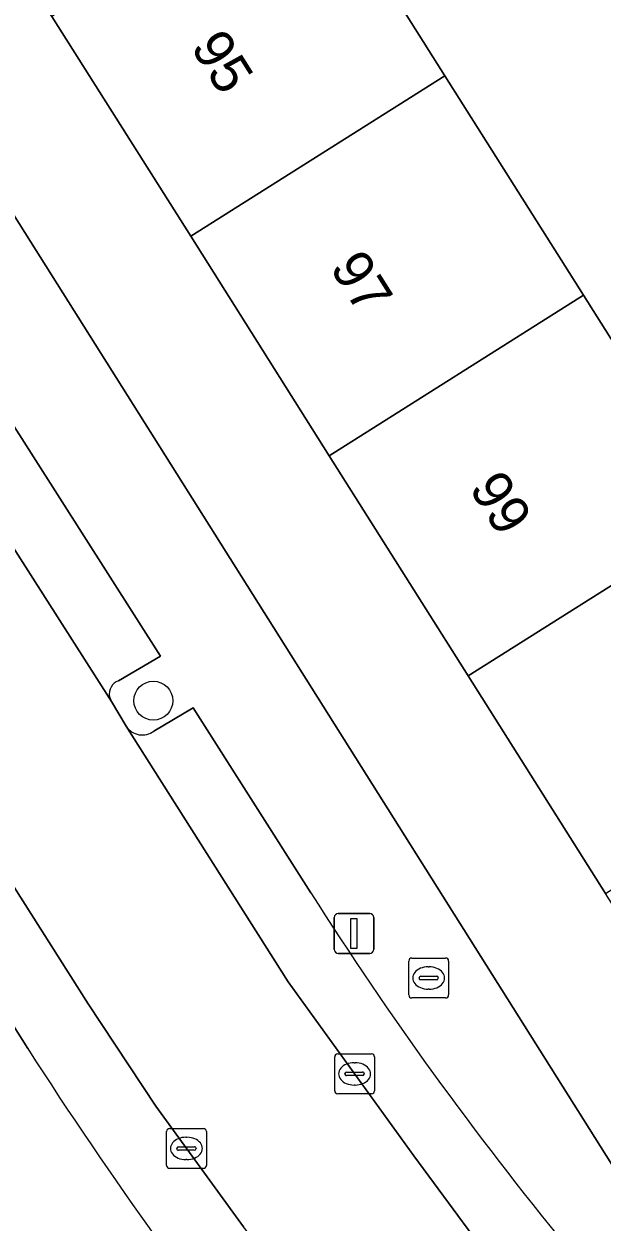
# Model space of a CAD drawing. Extents: x 162344 to 162869, y 381217 to 381818.
# Drawn here: x 162612.92 to 162627.44, y 381421.83 to 381451.9 of the extents above; entities that cross this region are included whole.
import ezdxf

# ---------------------------------------------------------------- set-up
doc = ezdxf.new("R2010")
doc.units = 0
for name, color, linetype in [('IMGEO_Boom', 7, 'Continuous'), ('IMGEO_Brandkraan', 7, 'Continuous'), ('IMGEO_Erf', 7, 'Continuous'), ('IMGEO_Kolk', 7, 'Continuous'), ('IMGEO_Lichtmast', 7, 'Continuous'), ('IMGEO_Pand', 7, 'Continuous'), ('IMGEO_Pand_nummerreeks', 7, 'Continuous'), ('IMGEO_Parkeervlak_open', 7, 'Continuous'), ('IMGEO_Rijbaan_lokaal_gesloten', 7, 'Continuous'), ('IMGEO_Voetpad_open', 7, 'Continuous')]:
    doc.layers.add(name, color=color, linetype=linetype)

msp = doc.modelspace()

# ---------------------------------------------------------------- linework, layer by layer
at = {"layer": 'IMGEO_Boom'}
msp.add_circle((162616.169, 381434.913), 0.489, dxfattribs=at)
at = {"layer": 'IMGEO_Brandkraan'}
for p, q in [((162622.582, 381427.527), (162622.582, 381428.379)), ((162622.657, 381428.453), (162623.509, 381428.453)), ((162623.583, 381428.379), (162623.583, 381427.527)), ((162622.884, 381427.996), (162623.282, 381427.996)), ((162623.07, 381428.233), (162623.095, 381428.233)), ((162622.841, 381427.947), (162622.841, 381427.959)), ((162623.279, 381427.91), (162622.881, 381427.91)), ((162623.093, 381427.673), (162623.068, 381427.673)), ((162623.325, 381427.959), (162623.325, 381427.947)), ((162623.509, 381427.453), (162622.657, 381427.453))]:
    msp.add_line(p, q, dxfattribs=at)
for points in [[(162622.582, 381427.527), (162622.582, 381428.379)], [(162622.657, 381428.453), (162623.509, 381428.453)], [(162623.583, 381428.379), (162623.583, 381427.527)], [(162623.509, 381427.453), (162622.657, 381427.453)]]:
    msp.add_lwpolyline(points, dxfattribs=at)
for centre, radius, start, end in [((162622.659, 381428.377), 0.0765, 91.552, 178.448), ((162622.659, 381428.377), 0.0765, 91.552, 178.448), ((162623.507, 381428.377), 0.0765, 1.552, 88.448), ((162623.507, 381428.377), 0.0765, 1.552, 88.448), ((162622.881, 381427.956), 0.0403, 85.8775, 175.7526), ((162623.286, 381427.958), 0.0386, 1.7309, 96.639), ((162622.878, 381427.946), 0.0366, 178.938, 274.7102), ((162623.282, 381427.953), 0.043, 264.8664, 352.4533), ((162622.659, 381427.529), 0.0765, 181.552, 268.448), ((162622.659, 381427.529), 0.0765, 181.552, 268.448), ((162623.507, 381427.529), 0.0765, 271.552, 358.448), ((162623.507, 381427.529), 0.0765, 271.552, 358.448)]:
    msp.add_arc(centre, radius, start, end, dxfattribs=at)
for centre, major_axis, ratio, start_param, end_param in [((162623.069, 381427.953), (-0.387, 0.002), 0.722429, 4.712389, 7.853982), ((162623.094, 381427.953), (-0.39, 0.002), 0.717154, 1.570796, 4.712389)]:
    msp.add_ellipse(centre, major_axis=major_axis, ratio=ratio, start_param=start_param, end_param=end_param, dxfattribs=at)
at = {"layer": 'IMGEO_Erf'}
msp.add_lwpolyline([(162613.96, 381479.407), (162607.642, 381473.555), (162608.933, 381472.289), (162609.55, 381472.679), (162613.084, 381467.082), (162616.593, 381461.525), (162620.009, 381456.115), (162623.492, 381450.599), (162626.971, 381445.09), (162630.46, 381439.564)], dxfattribs=at)
msp.add_lwpolyline([(162600.252, 381466.808), (162628.211, 381422.438), (162631.131, 381424.361), (162627.522, 381430.077), (162624.077, 381435.533), (162620.587, 381441.059), (162617.109, 381446.568), (162613.625, 381452.085), (162610.21, 381457.494), (162606.701, 381463.05), (162603.166, 381468.649)], close=True, dxfattribs=at)
at = {"layer": 'IMGEO_Kolk'}
for p, q in [((162620.723, 381425.121), (162620.723, 381425.973)), ((162620.798, 381426.047), (162621.65, 381426.047)), ((162621.724, 381425.973), (162621.724, 381425.121)), ((162621.025, 381425.59), (162621.423, 381425.59)), ((162621.211, 381425.827), (162621.236, 381425.827)), ((162620.982, 381425.541), (162620.982, 381425.553)), ((162621.42, 381425.504), (162621.022, 381425.504)), ((162621.234, 381425.267), (162621.209, 381425.267)), ((162621.466, 381425.553), (162621.466, 381425.541)), ((162621.65, 381425.047), (162620.798, 381425.047)), ((162616.501, 381423.25), (162616.501, 381424.102)), ((162616.576, 381424.176), (162617.428, 381424.176)), ((162617.502, 381424.102), (162617.502, 381423.25)), ((162616.989, 381423.956), (162617.014, 381423.956)), ((162616.76, 381423.67), (162616.76, 381423.682)), ((162617.198, 381423.633), (162616.8, 381423.633)), ((162616.803, 381423.719), (162617.201, 381423.719)), ((162617.244, 381423.682), (162617.244, 381423.67)), ((162617.428, 381423.176), (162616.576, 381423.176)), ((162617.012, 381423.396), (162616.987, 381423.396))]:
    msp.add_line(p, q, dxfattribs=at)
for points in [[(162620.723, 381425.121), (162620.723, 381425.973)], [(162620.798, 381426.047), (162621.65, 381426.047)], [(162621.724, 381425.973), (162621.724, 381425.121)], [(162621.65, 381425.047), (162620.798, 381425.047)], [(162616.501, 381423.25), (162616.501, 381424.102)], [(162616.576, 381424.176), (162617.428, 381424.176)], [(162617.502, 381424.102), (162617.502, 381423.25)], [(162617.428, 381423.176), (162616.576, 381423.176)]]:
    msp.add_lwpolyline(points, dxfattribs=at)
for centre, radius, start, end in [((162620.8, 381425.971), 0.0765, 91.552, 178.448), ((162620.8, 381425.971), 0.0765, 91.552, 178.448), ((162621.648, 381425.971), 0.0765, 1.552, 88.448), ((162621.648, 381425.971), 0.0765, 1.552, 88.448), ((162621.022, 381425.55), 0.0403, 85.8775, 175.7526), ((162621.427, 381425.552), 0.0386, 1.7309, 96.639), ((162621.019, 381425.54), 0.0366, 178.938, 274.7102), ((162621.423, 381425.547), 0.043, 264.8664, 352.4533), ((162620.8, 381425.123), 0.0765, 181.552, 268.448), ((162620.8, 381425.123), 0.0765, 181.552, 268.448), ((162621.648, 381425.123), 0.0765, 271.552, 358.448), ((162621.648, 381425.123), 0.0765, 271.552, 358.448), ((162616.578, 381424.1), 0.0765, 91.552, 178.448), ((162616.578, 381424.1), 0.0765, 91.552, 178.448), ((162617.426, 381424.1), 0.0765, 1.552, 88.448), ((162617.426, 381424.1), 0.0765, 1.552, 88.448), ((162616.8, 381423.679), 0.0403, 85.8775, 175.7526), ((162616.797, 381423.669), 0.0366, 178.938, 274.7102), ((162617.201, 381423.676), 0.043, 264.8664, 352.4533), ((162617.205, 381423.681), 0.0386, 1.7309, 96.639), ((162616.578, 381423.252), 0.0765, 181.552, 268.448), ((162616.578, 381423.252), 0.0765, 181.552, 268.448), ((162617.426, 381423.252), 0.0765, 271.552, 358.448), ((162617.426, 381423.252), 0.0765, 271.552, 358.448)]:
    msp.add_arc(centre, radius, start, end, dxfattribs=at)
for centre, major_axis, ratio, start_param, end_param in [((162621.21, 381425.547), (-0.387, 0.002), 0.722429, 4.712389, 7.853982), ((162621.235, 381425.547), (-0.39, 0.002), 0.717154, 1.570796, 4.712389), ((162616.988, 381423.676), (-0.387, 0.002), 0.722429, 4.712389, 7.853982), ((162617.013, 381423.676), (-0.39, 0.002), 0.717154, 1.570796, 4.712389)]:
    msp.add_ellipse(centre, major_axis=major_axis, ratio=ratio, start_param=start_param, end_param=end_param, dxfattribs=at)
at = {"layer": 'IMGEO_Lichtmast'}
for p, q in [((162620.812, 381429.572), (162621.602, 381429.572)), ((162621.602, 381429.572), (162620.812, 381429.572)), ((162620.712, 381428.672), (162620.712, 381429.472)), ((162620.712, 381429.472), (162620.712, 381428.672)), ((162621.702, 381429.472), (162621.702, 381428.672)), ((162621.702, 381428.672), (162621.702, 381429.472)), ((162621.602, 381428.572), (162620.812, 381428.572)), ((162620.812, 381428.572), (162621.602, 381428.572))]:
    msp.add_line(p, q, dxfattribs=at)
msp.add_lwpolyline([(162621.132, 381429.447), (162621.282, 381429.447), (162621.282, 381428.697), (162621.132, 381428.697), (162621.132, 381429.447)], dxfattribs=at)
for centre, start, end in [((162620.812, 381429.472), 90, 180), ((162620.812, 381429.472), 90, 180), ((162621.602, 381429.472), 0, 90), ((162621.602, 381429.472), 360, 90), ((162620.812, 381428.672), 180, 270), ((162620.812, 381428.672), 180, 270), ((162621.602, 381428.672), 270, 0), ((162621.602, 381428.672), 270, 0)]:
    msp.add_arc(centre, 0.1, start, end, dxfattribs=at)
at = {"layer": 'IMGEO_Pand'}
for points in [[(162623.492, 381450.599), (162620.009, 381456.115), (162613.625, 381452.085), (162617.109, 381446.568)], [(162623.492, 381450.599), (162617.109, 381446.568), (162620.587, 381441.059), (162626.971, 381445.09)], [(162630.46, 381439.564), (162626.971, 381445.09), (162620.587, 381441.059), (162624.077, 381435.533)], [(162630.46, 381439.564), (162624.077, 381435.533), (162627.522, 381430.077), (162633.906, 381434.108)]]:
    msp.add_lwpolyline(points, close=True, dxfattribs=at)
at = {"layer": 'IMGEO_Parkeervlak_open'}
for points in [[(162615.299, 381435.415), (162616.348, 381436.032), (162607.375, 381450.097), (162606.389, 381449.43)], [(162605.798, 381449.492), (162615.118, 381434.889), (162615.07, 381435.013)], [(162621.654, 381417.672), (162619.85, 381419.909), (162618.43, 381421.705), (162616.235, 381424.738), (162614.534, 381427.306), (162609.601, 381435.057), (162607.233, 381438.741), (162605.459, 381441.582)], [(162605.258, 381440.763), (162604.234, 381440.108), (162613.017, 381426.18)], [(162620.123, 381430.092), (162617.17, 381434.73), (162616.184, 381434.151)], [(162615.487, 381434.272), (162615.628, 381434.046), (162619.556, 381427.86), (162622.707, 381423.487), (162624.194, 381421.482), (162625.458, 381419.867)]]:
    msp.add_lwpolyline(points, dxfattribs=at)
for centre, radius, start, end in [((162615.422, 381435.079), 0.358, 110.1316, 190.5322), ((162615.892, 381434.536), 0.484, 213.1511, 307.152), ((162696.526, 381478.623), 90.513, 212.42387, 219.37604), ((162710.878, 381489.228), 116.412, 212.7918, 218.5007)]:
    msp.add_arc(centre, radius, start, end, dxfattribs=at)
at = {"layer": 'IMGEO_Rijbaan_lokaal_gesloten'}
msp.add_lwpolyline([(162624.194, 381421.482), (162622.707, 381423.487), (162619.556, 381427.86), (162615.628, 381434.046), (162615.487, 381434.272), (162615.118, 381434.889), (162605.798, 381449.492), (162605.481, 381449.991), (162601.154, 381456.882), (162596.087, 381464.752), (162596.011, 381464.87), (162593.509, 381468.912), (162589.756, 381466.45), (162596.967, 381454.988), (162603.511, 381444.701), (162605.459, 381441.582), (162607.233, 381438.741), (162609.601, 381435.057), (162614.534, 381427.306), (162616.235, 381424.738), (162618.43, 381421.705)], dxfattribs=at)
at = {"layer": 'IMGEO_Voetpad_open'}
for points in [[(162634.944, 381419.82), (162633.611, 381419.13), (162631.192, 381421.776), (162631.213, 381422.825), (162631.866, 381423.318), (162631.131, 381424.361), (162628.211, 381422.438), (162600.252, 381466.808), (162603.166, 381468.649), (162608.933, 381472.289), (162607.642, 381473.555), (162606.858, 381474.324), (162602.378, 381479.081), (162599.95, 381481.55)], [(162606.389, 381449.43), (162607.375, 381450.097), (162616.348, 381436.032), (162615.299, 381435.415)], [(162613.017, 381426.18), (162604.234, 381440.108), (162605.258, 381440.763)], [(162615.07, 381435.013), (162615.118, 381434.889), (162615.487, 381434.272)], [(162616.184, 381434.151), (162617.17, 381434.73), (162620.123, 381430.092)]]:
    msp.add_lwpolyline(points, dxfattribs=at)
for centre, radius, start, end in [((162615.422, 381435.079), 0.358, 110.1316, 190.5322), ((162615.892, 381434.536), 0.484, 213.1511, 307.152), ((162696.526, 381478.623), 90.513, 212.42387, 219.37604), ((162710.878, 381489.228), 116.412, 212.7918, 218.5007)]:
    msp.add_arc(centre, radius, start, end, dxfattribs=at)

# ---------------------------------------------------------------- texts
at = {"layer": 'IMGEO_Pand_nummerreeks'}
for s, p in [('95', (162617.091, 381451.317)), ('97', (162620.586, 381445.781)), ('99', (162624.082, 381440.245))]:
    msp.add_text(s, height=1, rotation=302.2698, dxfattribs=at).set_placement(p)

doc.saveas('drawing.dxf')
